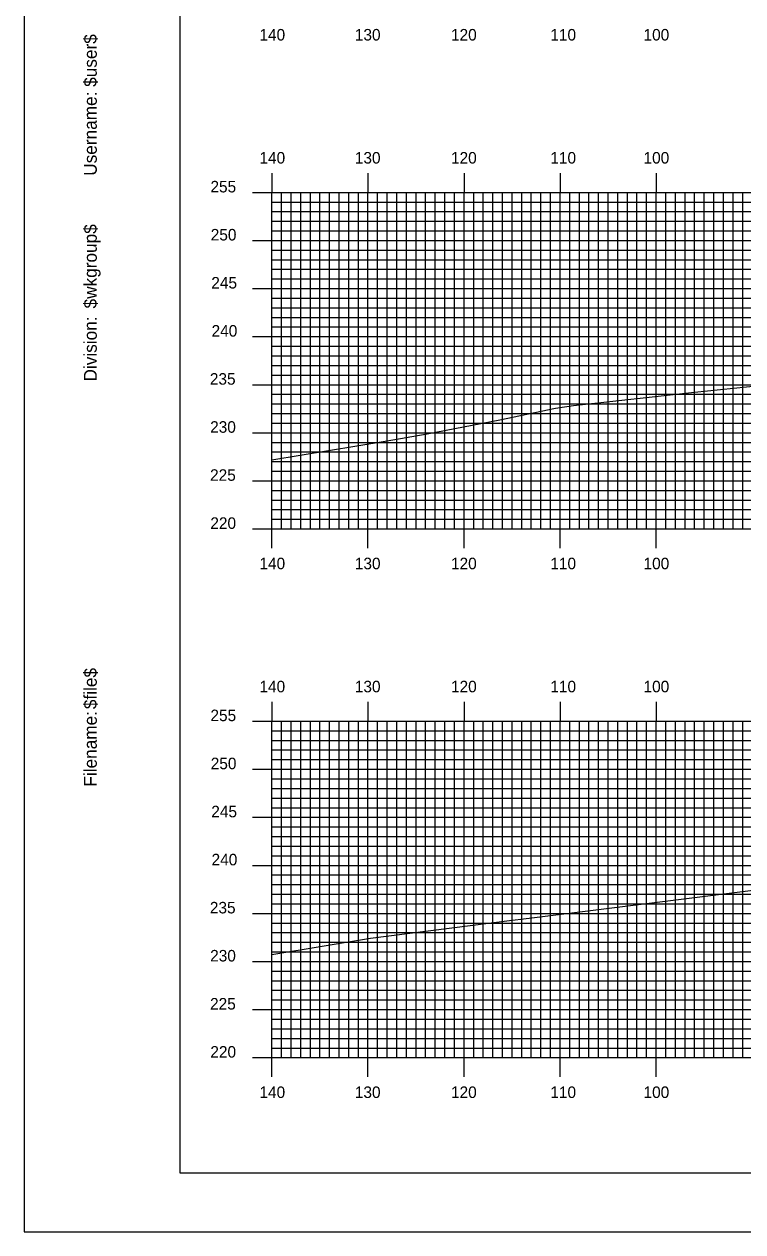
# Model space of a CAD drawing. Extents: x 1818063 to 1818407, y 442591 to 442811.
# Drawn here: x 1818063.3 to 1818138.1, y 442590.5 to 442716.2 of the extents above; entities that cross this region are included whole.
import ezdxf

# ---------------------------------------------------------------- set-up
doc = ezdxf.new("R2010")
doc.units = 0
for name, color, linetype in [('BORDER', 7, 'Continuous'), ('H_V ANNOTATION', 7, 'Continuous'), ('MAJOR', 7, 'Continuous'), ('MINOR', 7, 'Continuous'), ('PLOT BOUNDARY', 7, 'Continuous'), ('S_Roadway_Centerline', 7, 'Continuous')]:
    doc.layers.add(name, color=color, linetype=linetype)

msp = doc.modelspace()

# ---------------------------------------------------------------- linework, layer by layer
at = {"layer": 'BORDER'}
msp.add_lwpolyline([(1818079.53, 442596.67), (1818399.53, 442596.67), (1818399.53, 442806.67), (1818079.53, 442806.67)], close=True, dxfattribs=at)
at = {"layer": 'MAJOR'}
for p, q in [((1818089.13, 442700.67), (1818089.13, 442698.67)), ((1818099.13, 442700.67), (1818099.13, 442698.67)), ((1818109.13, 442700.67), (1818109.13, 442698.67)), ((1818119.13, 442700.67), (1818119.13, 442698.67)), ((1818129.13, 442700.67), (1818129.13, 442698.67)), ((1818087.12, 442698.67), (1818089.13, 442698.67)), ((1818089.13, 442698.67), (1818369.13, 442698.67)), ((1818089.13, 442663.67), (1818089.13, 442698.67)), ((1818089.13, 442663.67), (1818089.13, 442698.67)), ((1818089.13, 442698.67), (1818369.13, 442698.67)), ((1818099.13, 442663.67), (1818099.13, 442698.67)), ((1818109.13, 442663.67), (1818109.13, 442698.67)), ((1818119.13, 442663.67), (1818119.13, 442698.67)), ((1818129.13, 442663.67), (1818129.13, 442698.67)), ((1818087.12, 442693.67), (1818089.13, 442693.67)), ((1818089.13, 442693.67), (1818369.13, 442693.67)), ((1818087.12, 442688.67), (1818089.13, 442688.67)), ((1818089.13, 442688.67), (1818369.13, 442688.67)), ((1818087.12, 442683.67), (1818089.13, 442683.67)), ((1818089.13, 442683.67), (1818369.13, 442683.67)), ((1818087.12, 442678.67), (1818089.13, 442678.67)), ((1818089.13, 442678.67), (1818369.13, 442678.67)), ((1818087.12, 442673.67), (1818089.13, 442673.67)), ((1818089.13, 442673.67), (1818369.13, 442673.67)), ((1818087.12, 442668.67), (1818089.13, 442668.67)), ((1818089.13, 442668.67), (1818369.13, 442668.67)), ((1818087.12, 442663.67), (1818089.13, 442663.67)), ((1818089.13, 442663.67), (1818369.13, 442663.67)), ((1818089.13, 442663.67), (1818369.13, 442663.67)), ((1818089.13, 442661.66), (1818089.13, 442663.67)), ((1818099.13, 442661.66), (1818099.13, 442663.67)), ((1818109.13, 442661.66), (1818109.13, 442663.67)), ((1818119.13, 442661.66), (1818119.13, 442663.67)), ((1818129.13, 442661.66), (1818129.13, 442663.67)), ((1818089.13, 442645.67), (1818089.13, 442643.67)), ((1818099.13, 442645.67), (1818099.13, 442643.67)), ((1818109.13, 442645.67), (1818109.13, 442643.67)), ((1818119.13, 442645.67), (1818119.13, 442643.67)), ((1818129.13, 442645.67), (1818129.13, 442643.67)), ((1818087.12, 442643.67), (1818089.13, 442643.67)), ((1818089.13, 442643.67), (1818369.13, 442643.67)), ((1818089.13, 442608.67), (1818089.13, 442643.67)), ((1818089.13, 442608.67), (1818089.13, 442643.67)), ((1818089.13, 442643.67), (1818369.13, 442643.67)), ((1818099.13, 442608.67), (1818099.13, 442643.67)), ((1818109.13, 442608.67), (1818109.13, 442643.67)), ((1818119.13, 442608.67), (1818119.13, 442643.67)), ((1818129.13, 442608.67), (1818129.13, 442643.67)), ((1818087.12, 442638.67), (1818089.13, 442638.67)), ((1818089.13, 442638.67), (1818369.13, 442638.67)), ((1818087.12, 442633.67), (1818089.13, 442633.67)), ((1818089.13, 442633.67), (1818369.13, 442633.67)), ((1818087.12, 442628.67), (1818089.13, 442628.67)), ((1818089.13, 442628.67), (1818369.13, 442628.67)), ((1818087.12, 442623.67), (1818089.13, 442623.67)), ((1818089.13, 442623.67), (1818369.13, 442623.67)), ((1818087.12, 442618.67), (1818089.13, 442618.67)), ((1818089.13, 442618.67), (1818369.13, 442618.67)), ((1818087.12, 442613.67), (1818089.13, 442613.67)), ((1818089.13, 442613.67), (1818369.13, 442613.67)), ((1818087.12, 442608.67), (1818089.13, 442608.67)), ((1818089.13, 442608.67), (1818369.13, 442608.67)), ((1818089.13, 442608.67), (1818369.13, 442608.67)), ((1818089.13, 442606.66), (1818089.13, 442608.67)), ((1818099.13, 442606.66), (1818099.13, 442608.67)), ((1818109.13, 442606.66), (1818109.13, 442608.67)), ((1818119.13, 442606.66), (1818119.13, 442608.67)), ((1818129.13, 442606.66), (1818129.13, 442608.67))]:
    msp.add_line(p, q, dxfattribs=at)
at = {"layer": 'MINOR'}
for p, q in [((1818090.13, 442663.67), (1818090.13, 442698.67)), ((1818091.13, 442663.67), (1818091.13, 442698.67)), ((1818092.13, 442663.67), (1818092.13, 442698.67)), ((1818093.13, 442663.67), (1818093.13, 442698.67)), ((1818094.13, 442663.67), (1818094.13, 442698.67)), ((1818095.13, 442663.67), (1818095.13, 442698.67)), ((1818096.13, 442663.67), (1818096.13, 442698.67)), ((1818097.13, 442663.67), (1818097.13, 442698.67)), ((1818098.13, 442663.67), (1818098.13, 442698.67)), ((1818100.13, 442663.67), (1818100.13, 442698.67)), ((1818101.13, 442663.67), (1818101.13, 442698.67)), ((1818102.13, 442663.67), (1818102.13, 442698.67)), ((1818103.13, 442663.67), (1818103.13, 442698.67)), ((1818104.13, 442663.67), (1818104.13, 442698.67)), ((1818105.13, 442663.67), (1818105.13, 442698.67)), ((1818106.13, 442663.67), (1818106.13, 442698.67)), ((1818107.13, 442663.67), (1818107.13, 442698.67)), ((1818108.13, 442663.67), (1818108.13, 442698.67)), ((1818110.13, 442663.67), (1818110.13, 442698.67)), ((1818111.13, 442663.67), (1818111.13, 442698.67)), ((1818112.13, 442663.67), (1818112.13, 442698.67)), ((1818113.13, 442663.67), (1818113.13, 442698.67)), ((1818114.13, 442663.67), (1818114.13, 442698.67)), ((1818115.13, 442663.67), (1818115.13, 442698.67)), ((1818116.13, 442663.67), (1818116.13, 442698.67)), ((1818117.13, 442663.67), (1818117.13, 442698.67)), ((1818118.13, 442663.67), (1818118.13, 442698.67)), ((1818120.13, 442663.67), (1818120.13, 442698.67)), ((1818121.13, 442663.67), (1818121.13, 442698.67)), ((1818122.13, 442663.67), (1818122.13, 442698.67)), ((1818123.13, 442663.67), (1818123.13, 442698.67)), ((1818124.13, 442663.67), (1818124.13, 442698.67)), ((1818125.13, 442663.67), (1818125.13, 442698.67)), ((1818126.13, 442663.67), (1818126.13, 442698.67)), ((1818127.13, 442663.67), (1818127.13, 442698.67)), ((1818128.13, 442663.67), (1818128.13, 442698.67)), ((1818130.13, 442663.67), (1818130.13, 442698.67)), ((1818131.13, 442663.67), (1818131.13, 442698.67)), ((1818132.13, 442663.67), (1818132.13, 442698.67)), ((1818133.13, 442663.67), (1818133.13, 442698.67)), ((1818134.13, 442663.67), (1818134.13, 442698.67)), ((1818135.13, 442663.67), (1818135.13, 442698.67)), ((1818136.13, 442663.67), (1818136.13, 442698.67)), ((1818137.13, 442663.67), (1818137.13, 442698.67)), ((1818138.13, 442663.67), (1818138.13, 442698.67)), ((1818089.13, 442697.67), (1818369.13, 442697.67)), ((1818089.13, 442697.67), (1818091.13, 442697.67)), ((1818089.13, 442696.67), (1818369.13, 442696.67)), ((1818089.13, 442696.67), (1818091.13, 442696.67)), ((1818089.13, 442695.67), (1818369.13, 442695.67)), ((1818089.13, 442695.67), (1818091.13, 442695.67)), ((1818089.13, 442694.67), (1818369.13, 442694.67)), ((1818089.13, 442694.67), (1818091.13, 442694.67)), ((1818089.13, 442692.67), (1818369.13, 442692.67)), ((1818089.13, 442692.67), (1818091.13, 442692.67)), ((1818089.13, 442691.67), (1818369.13, 442691.67)), ((1818089.13, 442691.67), (1818091.13, 442691.67)), ((1818089.13, 442690.67), (1818369.13, 442690.67)), ((1818089.13, 442690.67), (1818091.13, 442690.67)), ((1818089.13, 442689.67), (1818369.13, 442689.67)), ((1818089.13, 442689.67), (1818091.13, 442689.67)), ((1818089.13, 442687.67), (1818369.13, 442687.67)), ((1818089.13, 442687.67), (1818091.13, 442687.67)), ((1818089.13, 442686.67), (1818369.13, 442686.67)), ((1818089.13, 442686.67), (1818091.13, 442686.67)), ((1818089.13, 442685.67), (1818369.13, 442685.67)), ((1818089.13, 442685.67), (1818091.13, 442685.67)), ((1818089.13, 442684.67), (1818369.13, 442684.67)), ((1818089.13, 442684.67), (1818091.13, 442684.67)), ((1818089.13, 442682.67), (1818369.13, 442682.67)), ((1818089.13, 442682.67), (1818091.13, 442682.67)), ((1818089.13, 442681.67), (1818369.13, 442681.67)), ((1818089.13, 442681.67), (1818091.13, 442681.67)), ((1818089.13, 442680.67), (1818369.13, 442680.67)), ((1818089.13, 442680.67), (1818091.13, 442680.67)), ((1818089.13, 442679.67), (1818369.13, 442679.67)), ((1818089.13, 442679.67), (1818091.13, 442679.67)), ((1818089.13, 442677.67), (1818369.13, 442677.67)), ((1818089.13, 442677.67), (1818091.13, 442677.67)), ((1818089.13, 442676.67), (1818369.13, 442676.67)), ((1818089.13, 442676.67), (1818091.13, 442676.67)), ((1818089.13, 442675.67), (1818369.13, 442675.67)), ((1818089.13, 442675.67), (1818091.13, 442675.67)), ((1818089.13, 442674.67), (1818369.13, 442674.67)), ((1818089.13, 442674.67), (1818091.13, 442674.67)), ((1818089.13, 442672.67), (1818369.13, 442672.67)), ((1818089.13, 442672.67), (1818091.13, 442672.67)), ((1818089.13, 442671.67), (1818369.13, 442671.67)), ((1818089.13, 442671.67), (1818091.13, 442671.67)), ((1818089.13, 442670.67), (1818369.13, 442670.67)), ((1818089.13, 442670.67), (1818091.13, 442670.67)), ((1818089.13, 442669.67), (1818369.13, 442669.67)), ((1818089.13, 442669.67), (1818091.13, 442669.67)), ((1818089.13, 442667.67), (1818369.13, 442667.67)), ((1818089.13, 442667.67), (1818091.13, 442667.67)), ((1818089.13, 442666.67), (1818369.13, 442666.67)), ((1818089.13, 442666.67), (1818091.13, 442666.67)), ((1818089.13, 442665.67), (1818369.13, 442665.67)), ((1818089.13, 442665.67), (1818091.13, 442665.67)), ((1818089.13, 442664.67), (1818369.13, 442664.67)), ((1818089.13, 442664.67), (1818091.13, 442664.67)), ((1818090.13, 442608.67), (1818090.13, 442643.67)), ((1818091.13, 442608.67), (1818091.13, 442643.67)), ((1818092.13, 442608.67), (1818092.13, 442643.67)), ((1818093.13, 442608.67), (1818093.13, 442643.67)), ((1818094.13, 442608.67), (1818094.13, 442643.67)), ((1818095.13, 442608.67), (1818095.13, 442643.67)), ((1818096.13, 442608.67), (1818096.13, 442643.67)), ((1818097.13, 442608.67), (1818097.13, 442643.67)), ((1818098.13, 442608.67), (1818098.13, 442643.67)), ((1818100.13, 442608.67), (1818100.13, 442643.67)), ((1818101.13, 442608.67), (1818101.13, 442643.67)), ((1818102.13, 442608.67), (1818102.13, 442643.67)), ((1818103.13, 442608.67), (1818103.13, 442643.67)), ((1818104.13, 442608.67), (1818104.13, 442643.67)), ((1818105.13, 442608.67), (1818105.13, 442643.67)), ((1818106.13, 442608.67), (1818106.13, 442643.67)), ((1818107.13, 442608.67), (1818107.13, 442643.67)), ((1818108.13, 442608.67), (1818108.13, 442643.67)), ((1818110.13, 442608.67), (1818110.13, 442643.67)), ((1818111.13, 442608.67), (1818111.13, 442643.67)), ((1818112.13, 442608.67), (1818112.13, 442643.67)), ((1818113.13, 442608.67), (1818113.13, 442643.67)), ((1818114.13, 442608.67), (1818114.13, 442643.67)), ((1818115.13, 442608.67), (1818115.13, 442643.67)), ((1818116.13, 442608.67), (1818116.13, 442643.67)), ((1818117.13, 442608.67), (1818117.13, 442643.67)), ((1818118.13, 442608.67), (1818118.13, 442643.67)), ((1818120.13, 442608.67), (1818120.13, 442643.67)), ((1818121.13, 442608.67), (1818121.13, 442643.67)), ((1818122.13, 442608.67), (1818122.13, 442643.67)), ((1818123.13, 442608.67), (1818123.13, 442643.67)), ((1818124.13, 442608.67), (1818124.13, 442643.67)), ((1818125.13, 442608.67), (1818125.13, 442643.67)), ((1818126.13, 442608.67), (1818126.13, 442643.67)), ((1818127.13, 442608.67), (1818127.13, 442643.67)), ((1818128.13, 442608.67), (1818128.13, 442643.67)), ((1818130.13, 442608.67), (1818130.13, 442643.67)), ((1818131.13, 442608.67), (1818131.13, 442643.67)), ((1818132.13, 442608.67), (1818132.13, 442643.67)), ((1818133.13, 442608.67), (1818133.13, 442643.67)), ((1818134.13, 442608.67), (1818134.13, 442643.67)), ((1818135.13, 442608.67), (1818135.13, 442643.67)), ((1818136.13, 442608.67), (1818136.13, 442643.67)), ((1818137.13, 442608.67), (1818137.13, 442643.67)), ((1818138.13, 442608.67), (1818138.13, 442643.67)), ((1818089.13, 442642.67), (1818369.13, 442642.67)), ((1818089.13, 442642.67), (1818091.13, 442642.67)), ((1818089.13, 442641.67), (1818369.13, 442641.67)), ((1818089.13, 442641.67), (1818091.13, 442641.67)), ((1818089.13, 442640.67), (1818369.13, 442640.67)), ((1818089.13, 442640.67), (1818091.13, 442640.67)), ((1818089.13, 442639.67), (1818369.13, 442639.67)), ((1818089.13, 442639.67), (1818091.13, 442639.67)), ((1818089.13, 442637.67), (1818369.13, 442637.67)), ((1818089.13, 442637.67), (1818091.13, 442637.67)), ((1818089.13, 442636.67), (1818369.13, 442636.67)), ((1818089.13, 442636.67), (1818091.13, 442636.67)), ((1818089.13, 442635.67), (1818369.13, 442635.67)), ((1818089.13, 442635.67), (1818091.13, 442635.67)), ((1818089.13, 442634.67), (1818369.13, 442634.67)), ((1818089.13, 442634.67), (1818091.13, 442634.67)), ((1818089.13, 442632.67), (1818369.13, 442632.67)), ((1818089.13, 442632.67), (1818091.13, 442632.67)), ((1818089.13, 442631.67), (1818369.13, 442631.67)), ((1818089.13, 442631.67), (1818091.13, 442631.67)), ((1818089.13, 442630.67), (1818369.13, 442630.67)), ((1818089.13, 442630.67), (1818091.13, 442630.67)), ((1818089.13, 442629.67), (1818369.13, 442629.67)), ((1818089.13, 442629.67), (1818091.13, 442629.67)), ((1818089.13, 442627.67), (1818369.13, 442627.67)), ((1818089.13, 442627.67), (1818091.13, 442627.67)), ((1818089.13, 442626.67), (1818369.13, 442626.67)), ((1818089.13, 442626.67), (1818091.13, 442626.67)), ((1818089.13, 442625.67), (1818369.13, 442625.67)), ((1818089.13, 442625.67), (1818091.13, 442625.67)), ((1818089.13, 442624.67), (1818369.13, 442624.67)), ((1818089.13, 442624.67), (1818091.13, 442624.67)), ((1818089.13, 442622.67), (1818369.13, 442622.67)), ((1818089.13, 442622.67), (1818091.13, 442622.67)), ((1818089.13, 442621.67), (1818369.13, 442621.67)), ((1818089.13, 442621.67), (1818091.13, 442621.67)), ((1818089.13, 442620.67), (1818369.13, 442620.67)), ((1818089.13, 442620.67), (1818091.13, 442620.67)), ((1818089.13, 442619.67), (1818369.13, 442619.67)), ((1818089.13, 442619.67), (1818091.13, 442619.67)), ((1818089.13, 442617.67), (1818369.13, 442617.67)), ((1818089.13, 442617.67), (1818091.13, 442617.67)), ((1818089.13, 442616.67), (1818369.13, 442616.67)), ((1818089.13, 442616.67), (1818091.13, 442616.67)), ((1818089.13, 442615.67), (1818369.13, 442615.67)), ((1818089.13, 442615.67), (1818091.13, 442615.67)), ((1818089.13, 442614.67), (1818369.13, 442614.67)), ((1818089.13, 442614.67), (1818091.13, 442614.67)), ((1818089.13, 442612.67), (1818369.13, 442612.67)), ((1818089.13, 442612.67), (1818091.13, 442612.67)), ((1818089.13, 442611.67), (1818369.13, 442611.67)), ((1818089.13, 442611.67), (1818091.13, 442611.67)), ((1818089.13, 442610.67), (1818369.13, 442610.67)), ((1818089.13, 442610.67), (1818091.13, 442610.67)), ((1818089.13, 442609.67), (1818369.13, 442609.67)), ((1818089.13, 442609.67), (1818091.13, 442609.67))]:
    msp.add_line(p, q, dxfattribs=at)
at = {"layer": 'PLOT BOUNDARY'}
msp.add_lwpolyline([(1818063.34, 442590.55), (1818403.34, 442590.55), (1818403.34, 442810.55), (1818063.34, 442810.55)], close=True, dxfattribs=at)
at = {"layer": 'S_Roadway_Centerline'}
for points in [[(1818089.13, 442670.86), (1818100.91, 442672.8), (1818105.29, 442673.54), (1818112.85, 442675.02), (1818118.64, 442676.23), (1818120.53, 442676.51), (1818133.11, 442677.89), (1818139.88, 442678.59), (1818164.83, 442681.85), (1818170.67, 442682.57), (1818171.78, 442682.7), (1818175.73, 442683.27), (1818187.98, 442684.69), (1818198.58, 442685.89), (1818204.4, 442686.48), (1818214.15, 442686.97), (1818225.54, 442687.62), (1818238.58, 442688.41), (1818240.99, 442688.51), (1818252.33, 442688.95), (1818255.97, 442689.14), (1818265.92, 442689.77)], [(1818089.13, 442619.38), (1818099.38, 442621.1), (1818113.86, 442622.94), (1818115.04, 442623.07), (1818116.47, 442623.23), (1818143.95, 442626.67), (1818155.52, 442627.86), (1818167.43, 442629.55), (1818182.08, 442630.7), (1818182.46, 442630.73), (1818182.54, 442630.74), (1818196.08, 442631.87), (1818199.69, 442632.1), (1818206.98, 442632.46), (1818218, 442633.06), (1818232.25, 442633.81), (1818234.77, 442633.98), (1818236.39, 442633.98), (1818245.22, 442634.08), (1818251.33, 442634.17), (1818252.39, 442634.21), (1818254.12, 442634.29), (1818267.71, 442635.24)]]:
    msp.add_lwpolyline(points, dxfattribs=at)

# ---------------------------------------------------------------- texts
at = {"layer": 'BORDER'}
for s, p in [('$user$', (1818070.9, 442709.65)), ('Username:', (1818070.9, 442700.4)), ('$wkgroup$', (1818070.9, 442686.6)), ('Division:', (1818070.9, 442679)), ('$file$', (1818070.9, 442644.92)), ('Filename:', (1818070.9, 442636.86))]:
    msp.add_text(s, height=1.339, rotation=90, dxfattribs=at).set_placement(p)
at = {"layer": 'H_V ANNOTATION'}
for s, p in [('140', (1818087.83, 442714.47)), ('130', (1818097.76, 442714.47)), ('120', (1818107.77, 442714.47)), ('110', (1818118.11, 442714.47)), ('100', (1818127.81, 442714.47)), ('140', (1818087.83, 442701.67)), ('130', (1818097.76, 442701.67)), ('120', (1818107.77, 442701.67)), ('110', (1818118.11, 442701.67)), ('100', (1818127.81, 442701.67)), ('255', (1818082.73, 442698.67)), ('250', (1818082.76, 442693.67)), ('245', (1818082.82, 442688.67)), ('240', (1818082.85, 442683.67)), ('235', (1818082.67, 442678.67)), ('230', (1818082.7, 442673.67)), ('225', (1818082.69, 442668.67)), ('220', (1818082.72, 442663.67)), ('140', (1818087.83, 442659.47)), ('130', (1818097.76, 442659.47)), ('120', (1818107.77, 442659.47)), ('110', (1818118.11, 442659.47)), ('100', (1818127.81, 442659.47)), ('140', (1818087.83, 442646.67)), ('130', (1818097.76, 442646.67)), ('120', (1818107.77, 442646.67)), ('110', (1818118.11, 442646.67)), ('100', (1818127.81, 442646.67)), ('255', (1818082.73, 442643.67)), ('250', (1818082.76, 442638.67)), ('245', (1818082.82, 442633.67)), ('240', (1818082.85, 442628.67)), ('235', (1818082.67, 442623.67)), ('230', (1818082.7, 442618.67)), ('225', (1818082.69, 442613.67)), ('220', (1818082.72, 442608.67)), ('140', (1818087.83, 442604.47)), ('130', (1818097.76, 442604.47)), ('120', (1818107.77, 442604.47)), ('110', (1818118.11, 442604.47)), ('100', (1818127.81, 442604.47))]:
    msp.add_text(s, height=1.2, dxfattribs=at).set_placement(p)
at = {"layer": 'MAJOR'}
for p in [(1818089.12, 442663.67), (1818089.12, 442608.67)]:
    msp.add_text('-', height=0.012, dxfattribs=at).set_placement(p)

doc.saveas('drawing.dxf')
